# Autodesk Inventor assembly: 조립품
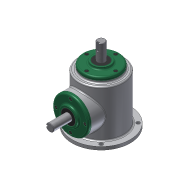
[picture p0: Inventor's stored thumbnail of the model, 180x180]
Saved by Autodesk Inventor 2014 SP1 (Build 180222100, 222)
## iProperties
Created: 2014-10
Part Number: 조립품
Document SubType Name: Assembly
Designer: KYOUNG IL JANG
Author: KYOUNG IL JANG
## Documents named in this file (8)
- D:\20_MDU\10_기술자격시험\20_Inventor\2014-10월 출제중\2급\조립품.iam
- D:\20_MDU\10_기술자격시험\20_Inventor\2014-10월 출제중\2급\1.본체.ipt
- D:\20_MDU\10_기술자격시험\20_Inventor\2014-10월 출제중\2급\메인축어셈블리.iam
- D:\20_MDU\10_기술자격시험\20_Inventor\2014-10월 출제중\2급\서브축어셈블리.iam
- D:\20_MDU\10_기술자격시험\20_Inventor\2014-10월 출제중\2급\베어링 6203.ipt
- D:\20_MDU\10_기술자격시험\20_Inventor\2014-10월 출제중\2급\커버.ipt
- D:\20_MDU\10_기술자격시험\20_Inventor\2014-10월 출제중\2급\오일실.ipt
- D:\20_MDU\10_기술자격시험\20_Inventor\2014-10월 출제중\2급\M4.ipt
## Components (9 placed, 2 different names)
1. 1.본체:1 — 플러쉬:1, 플러쉬:2, 각도:2
2. M4:1
3. M4:2
4. M4:3
5. M4:4
6. M4:5
7. M4:6
8. M4:7
9. M4:8
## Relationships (3: Flush 2, Angle 1)
- 플러쉬:1 [Flush]: 1.본체:1
- 플러쉬:2 [Flush]: 1.본체:1
- 각도:2 [Angle]: 1.본체:1
